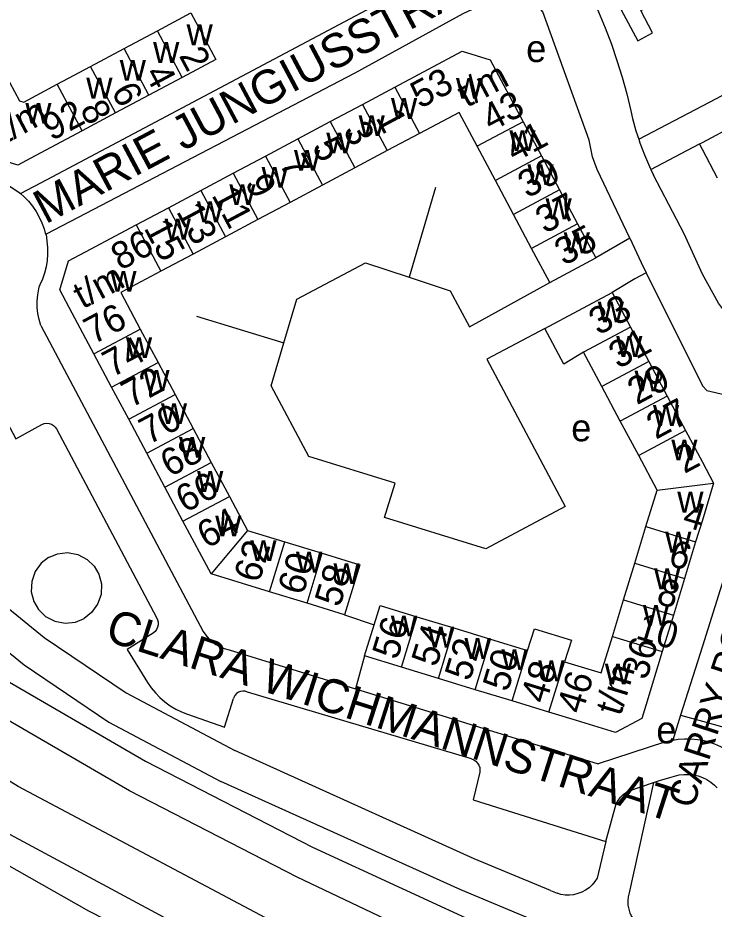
# Model space of a CAD drawing. Extents: x 159902 to 161769, y 383692 to 384875.
# Drawn here: x 160598.8 to 160701.7, y 383771.4 to 383903 of the extents above; entities that cross this region are included whole.
import ezdxf

# ---------------------------------------------------------------- set-up
doc = ezdxf.new("R2010")
doc.units = 0
for name, color, linetype in [('BLT_Basislijn', 7, 'Continuous'), ('BLT_Bebouwing', 7, 'Continuous'), ('BLT_Centroide', 7, 'Continuous'), ('BLT_Huisnummer', 7, 'Continuous'), ('BLT_Huisnummer_ tussenligend', 7, 'Continuous'), ('BLT_Huisnummer_reeks', 7, 'Continuous'), ('BLT_Onderverdeling_panden', 7, 'Continuous'), ('BLT_Spoorlijn', 7, 'Continuous'), ('BLT_Straatnaam', 7, 'Continuous'), ('BLT_Straatnaam_verkleind', 7, 'Continuous')]:
    doc.layers.add(name, color=color, linetype=linetype)

msp = doc.modelspace()

# ---------------------------------------------------------------- linework, layer by layer
at = {"layer": 'BLT_Basislijn'}
for p, q in [((160700, 383890.04), (160746.59, 383914.49)), ((160690.61, 383885.08), (160700, 383890.04)), ((160692.39, 383880.62), (160699.57, 383884.4)), ((160692.39, 383880.62), (160692.79, 383879.79)), ((160599.22, 383877.05), (160603.18, 383879.15)), ((160660.56, 383877.98), (160656.69, 383864.7)), ((160606.51, 383872.87), (160603.03, 383871.05)), ((160689.27, 383870.48), (160684.24, 383867.55)), ((160691.72, 383865.36), (160700, 383848.64)), ((160625.22, 383858.96), (160638.15, 383855)), ((160602.22, 383857.56), (160626.24, 383812.37)), ((160604.52, 383842.33), (160619.33, 383814.43)), ((160647.11, 383814.85), (160651.5, 383813.38)), ((160700, 383810.22), (160696.79, 383800)), ((160630.04, 383809.66), (160648.74, 383803.9)), ((160650.08, 383808.76), (160648.74, 383803.9)), ((160665.88, 383793.57), (160632.75, 383803.43)), ((160648.74, 383803.9), (160684.61, 383792.85)), ((160696.79, 383800), (160695.64, 383796.34)), ((160696.79, 383800), (160700, 383799.11)), ((160700, 383799.11), (160704.39, 383797.89)), ((160694.57, 383796.09), (160684.61, 383792.85)), ((160667.1, 383791.62), (160666.13, 383787.5)), ((160689.04, 383788.79), (160692.78, 383790.07)), ((160692.78, 383790.07), (160689.16, 383773.78)), ((160692.78, 383790.07), (160693.67, 383790.37)), ((160693.67, 383790.37), (160695.21, 383790.79)), ((160666.13, 383787.5), (160685.72, 383781.35)), ((160685.72, 383781.35), (160687.26, 383786.93)), ((160685.72, 383781.35), (160684.46, 383775.96)), ((160642.4, 383780.51), (160683.65, 383761.53)), ((160677.54, 383774.1), (160678.55, 383773.7))]:
    msp.add_line(p, q, dxfattribs=at)
for points in [[(160681.26, 383910.86), (160682.46, 383908.59), (160683.59, 383906.28), (160684.65, 383903.93), (160685.64, 383901.56), (160686.55, 383899.15), (160687.38, 383896.72), (160688.14, 383894.26), (160688.83, 383891.78), (160689.43, 383889.28), (160689.68, 383888.16)], [(160689.27, 383870.48), (160684.45, 383880.61), (160683.78, 383882.49), (160683.26, 383884.97), (160676.41, 383903.93), (160674.94, 383905.66), (160673.06, 383906.41), (160670.67, 383906.49), (160664.62, 383903.62), (160648.63, 383894.85), (160606.51, 383872.87)], [(160603.18, 383879.15), (160651.15, 383904.6), (160651.93, 383905.02)], [(160785.77, 383902.89), (160787.4, 383898.79), (160793.37, 383890.07), (160793.61, 383887.33), (160792.51, 383884.49), (160789.92, 383882.31), (160785.09, 383879.14), (160780.99, 383877.27), (160776.2, 383874.72), (160756.99, 383863.99), (160732.18, 383850.87), (160729.15, 383850.07), (160725.97, 383850.07), (160724.04, 383850.51), (160723.96, 383850.67), (160708.54, 383855.73), (160705.6, 383857.28), (160703.88, 383858.91), (160702.38, 383860.87), (160700, 383865.16)], [(160689.68, 383888.16), (160690.19, 383886.35), (160690.61, 383885.08)], [(160690.61, 383885.08), (160690.78, 383884.56), (160691.44, 383882.8), (160692.18, 383881.07), (160692.39, 383880.62)], [(160494.74, 383882.47), (160534.14, 383847.21), (160538.7, 383844.28), (160543.1, 383841.91), (160550.59, 383840.28), (160557.96, 383839.05), (160562.54, 383837.97), (160575.03, 383827.56), (160599.76, 383807.45), (160612.28, 383798.99), (160628.85, 383790.24)], [(160700, 383865.16), (160697.3, 383871.1), (160692.79, 383879.79)], [(160595.73, 383879.04), (160596.61, 383878.69), (160597.46, 383878.27), (160598.26, 383877.78), (160599.03, 383877.22), (160599.22, 383877.05)], [(160599.22, 383877.05), (160599.74, 383876.6), (160600.4, 383875.92), (160601, 383875.19), (160601.53, 383874.41), (160602, 383873.59), (160602.39, 383872.73), (160602.71, 383871.84), (160602.94, 383871.01)], [(160603.03, 383871.05), (160603.21, 383869.05), (160603.22, 383868.11), (160603.15, 383867.17), (160603, 383866.23), (160602.77, 383865.32), (160602.46, 383864.42), (160602.08, 383863.56), (160602.03, 383863.45)], [(160689.27, 383870.48), (160690.96, 383866.88), (160691.72, 383865.36)], [(160638.15, 383855), (160640.06, 383861.45), (160650.19, 383866.85), (160656.69, 383864.7)], [(160691.72, 383865.36), (160690, 383864.48), (160686.66, 383862.43)], [(160656.69, 383864.7), (160662.72, 383862.7), (160665.59, 383857.4), (160677.44, 383863.93)], [(160602.22, 383857.56), (160601.97, 383858.44), (160601.8, 383859.34), (160601.71, 383860.25), (160601.7, 383861.17), (160601.77, 383862.08), (160601.92, 383862.98), (160602.03, 383863.45)], [(160588.63, 383859.42), (160598.52, 383840.83), (160602.38, 383842.97)], [(160676.73, 383857.15), (160668.15, 383852.6), (160679.7, 383830.83), (160667.99, 383824.59), (160653.04, 383829.22), (160654.59, 383834.29), (160641.82, 383838.24), (160636.28, 383848.68), (160638.15, 383855)], [(160700, 383848.64), (160700.67, 383847.99), (160705.56, 383846.86), (160706.89, 383846.34), (160708.7, 383844.59), (160709.23, 383843.12), (160709.29, 383840.38), (160707.84, 383835.19), (160700, 383810.22)], [(160602.38, 383842.97), (160602.72, 383843.09), (160603.08, 383843.14), (160603.44, 383843.1), (160603.79, 383842.99), (160604.1, 383842.8), (160604.36, 383842.55), (160604.52, 383842.33)], [(160685.49, 383755.81), (160663.23, 383765.09), (160640.11, 383776.07), (160615.32, 383788.84), (160570.09, 383815.07), (160559.86, 383821.42), (160549.35, 383829.03)], [(160603.38, 383823.31), (160602.27, 383822.45), (160601.38, 383821.23), (160600.88, 383819.75), (160600.82, 383818.21), (160601.19, 383816.8), (160601.88, 383815.61), (160602.93, 383814.59), (160604.3, 383813.88), (160605.84, 383813.6), (160607.34, 383813.77), (160608.63, 383814.3)], [(160603.38, 383823.31), (160604.67, 383823.85), (160606.17, 383824.02), (160607.71, 383823.74), (160609.07, 383823.02), (160610.12, 383822.01), (160610.82, 383820.82), (160611.19, 383819.41), (160611.13, 383817.86), (160610.62, 383816.39), (160609.74, 383815.17), (160608.63, 383814.3)], [(160590.85, 383821.13), (160602.74, 383811.47), (160614.85, 383803.29), (160630.92, 383794.79)], [(160572.6, 383819.39), (160617.72, 383793.23), (160642.4, 383780.51)], [(160619.33, 383814.43), (160619.48, 383814.09), (160619.56, 383813.73), (160619.56, 383813.36), (160619.49, 383813), (160619.33, 383812.66), (160619.11, 383812.37), (160618.81, 383812.12)], [(160626.24, 383812.37), (160626.62, 383811.81), (160627.06, 383811.3), (160627.56, 383810.84), (160628.11, 383810.44), (160628.71, 383810.11), (160629.34, 383809.85), (160630.04, 383809.66)], [(160618.81, 383812.12), (160615.01, 383809.71), (160618, 383804.82)], [(160618, 383804.82), (160618.55, 383804.03), (160619.17, 383803.29), (160619.84, 383802.61), (160620.57, 383801.98), (160621.35, 383801.41), (160622.17, 383800.91), (160623.03, 383800.49), (160623.89, 383800.14)], [(160632.75, 383803.43), (160632.43, 383803.54), (160632.08, 383803.57), (160631.74, 383803.52), (160631.43, 383803.39), (160631.15, 383803.2), (160630.92, 383802.94), (160630.76, 383802.64), (160630.7, 383802.46)], [(160623.89, 383800.14), (160629.35, 383798.24), (160630.7, 383802.46)], [(160695.64, 383796.34), (160696.43, 383796.47), (160697.38, 383796.54), (160698.33, 383796.53), (160699.27, 383796.43), (160700, 383796.31)], [(160694.57, 383796.09), (160695.49, 383796.32), (160695.64, 383796.34)], [(160700, 383796.31), (160700.92, 383796.08), (160701.82, 383795.77), (160702.69, 383795.39), (160703.53, 383794.94)], [(160677.54, 383774.1), (160666.29, 383778.79), (160630.92, 383794.79)], [(160665.88, 383793.57), (160666.23, 383793.43), (160666.53, 383793.22), (160666.78, 383792.95), (160666.97, 383792.63), (160667.09, 383792.28), (160667.12, 383791.91), (160667.1, 383791.62)], [(160695.21, 383790.79), (160695.87, 383791.02), (160696.56, 383791.18), (160697.26, 383791.27), (160697.97, 383791.27), (160698.67, 383791.19), (160699.36, 383791.03), (160700, 383790.81)], [(160686.08, 383765.12), (160664.3, 383774.2), (160628.85, 383790.24)], [(160700, 383790.81), (160700.64, 383790.5), (160701.23, 383790.13), (160701.79, 383789.69), (160702.21, 383789.27)], [(160687.26, 383786.93), (160687.54, 383787.43), (160687.9, 383787.89), (160688.32, 383788.3), (160688.78, 383788.64), (160689.04, 383788.79)], [(160684.46, 383775.96), (160684.12, 383775.43), (160683.71, 383774.95), (160683.25, 383774.53), (160682.74, 383774.17), (160682.18, 383773.87), (160681.59, 383773.65), (160680.98, 383773.5), (160680.35, 383773.44), (160679.73, 383773.45), (160679.1, 383773.54), (160678.55, 383773.7)], [(160689.16, 383773.78), (160689.03, 383773.18), (160688.98, 383772.57), (160689.01, 383771.95), (160689.12, 383771.35), (160689.3, 383770.76), (160689.57, 383770.21), (160689.9, 383769.69), (160690.29, 383769.22), (160690.74, 383768.8), (160691.25, 383768.45), (160691.75, 383768.19)]]:
    msp.add_lwpolyline(points, dxfattribs=at)
at = {"layer": 'BLT_Bebouwing'}
for p, q in [((160614.53, 383898.48), (160619.47, 383901.11)), ((160609.59, 383895.84), (160614.53, 383898.48)), ((160604.65, 383893.21), (160609.59, 383895.84)), ((160623.14, 383894.23), (160618.2, 383891.6)), ((160649.77, 383890.24), (160654.55, 383892.79)), ((160618.2, 383891.6), (160613.26, 383888.97)), ((160644.99, 383887.7), (160649.77, 383890.24)), ((160613.26, 383888.97), (160608.32, 383886.34)), ((160640.21, 383885.15), (160644.99, 383887.7)), ((160673.54, 383887.66), (160676.21, 383882.63)), ((160700, 383884.62), (160706.39, 383888.02)), ((160608.32, 383886.34), (160601.39, 383882.65)), ((160635.43, 383882.61), (160640.21, 383885.15)), ((160658.19, 383885.94), (160653.42, 383883.4)), ((160669.41, 383879.01), (160666.73, 383884.04)), ((160699.57, 383884.4), (160700, 383884.62)), ((160700, 383883.59), (160699.57, 383884.4)), ((160702.26, 383879.33), (160700, 383883.59)), ((160630.65, 383880.06), (160635.43, 383882.61)), ((160653.42, 383883.4), (160648.64, 383880.85)), ((160676.21, 383882.63), (160678.89, 383877.61)), ((160648.64, 383880.85), (160643.86, 383878.3)), ((160625.87, 383877.52), (160630.65, 383880.06)), ((160643.86, 383878.3), (160639.08, 383875.76)), ((160672.09, 383873.98), (160669.41, 383879.01)), ((160621.09, 383874.97), (160625.87, 383877.52)), ((160678.89, 383877.61), (160681.57, 383872.58)), ((160639.08, 383875.76), (160634.3, 383873.22)), ((160616.31, 383872.43), (160621.09, 383874.97)), ((160634.3, 383873.22), (160629.52, 383870.67)), ((160674.77, 383868.96), (160672.09, 383873.98)), ((160608.85, 383868.45), (160616.31, 383872.43)), ((160681.57, 383872.58), (160684.24, 383867.55)), ((160629.52, 383870.67), (160624.74, 383868.12)), ((160677.44, 383863.93), (160674.77, 383868.96)), ((160624.74, 383868.12), (160619.96, 383865.58)), ((160677.44, 383863.93), (160684.24, 383867.55)), ((160676.73, 383857.15), (160686.66, 383862.43)), ((160686.66, 383862.43), (160689.38, 383857.33)), ((160610.06, 383853.38), (160606.85, 383859.41)), ((160689.38, 383857.33), (160692.09, 383852.24)), ((160616.93, 383857.03), (160619.56, 383852.1)), ((160612.69, 383848.45), (160610.06, 383853.38)), ((160685.16, 383848.54), (160682.44, 383853.64)), ((160619.56, 383852.1), (160622.07, 383847.38)), ((160692.09, 383852.24), (160694.81, 383847.14)), ((160615.21, 383843.72), (160612.69, 383848.45)), ((160687.87, 383843.45), (160685.16, 383848.54)), ((160622.07, 383847.38), (160624.75, 383842.36)), ((160694.81, 383847.14), (160697.52, 383842.05)), ((160617.88, 383838.7), (160615.21, 383843.72)), ((160690.59, 383838.35), (160687.87, 383843.45)), ((160624.75, 383842.36), (160627.42, 383837.34)), ((160697.52, 383842.05), (160700, 383837.39)), ((160620.55, 383833.69), (160617.88, 383838.7)), ((160627.42, 383837.34), (160630.09, 383832.33)), ((160693.3, 383833.26), (160690.59, 383838.35)), ((160700, 383837.39), (160701.66, 383834.28)), ((160623.23, 383828.67), (160620.55, 383833.69)), ((160701.66, 383834.28), (160700, 383828.84)), ((160630.09, 383832.33), (160632.76, 383827.31)), ((160691.65, 383827.86), (160693.3, 383833.26)), ((160627.38, 383820.88), (160623.23, 383828.67)), ((160700, 383828.84), (160699.01, 383825.61)), ((160632.76, 383827.31), (160638.3, 383825.62)), ((160690, 383822.46), (160691.65, 383827.86)), ((160638.3, 383825.62), (160643.83, 383823.93)), ((160699.01, 383825.61), (160697.37, 383820.21)), ((160688.36, 383817.05), (160690, 383822.46)), ((160636.04, 383818.23), (160627.38, 383820.88)), ((160697.37, 383820.21), (160695.72, 383814.81)), ((160641.58, 383816.54), (160636.04, 383818.23)), ((160686.71, 383811.65), (160688.36, 383817.05)), ((160657.81, 383814.56), (160663.26, 383812.9)), ((160695.72, 383814.81), (160694.07, 383809.41)), ((160663.26, 383812.9), (160668.71, 383811.24)), ((160668.71, 383811.24), (160674.16, 383809.58)), ((160694.07, 383809.41), (160691.64, 383801.43)), ((160660.99, 383805.43), (160655.54, 383807.09)), ((160666.43, 383803.77), (160660.99, 383805.43)), ((160671.88, 383802.11), (160666.43, 383803.77)), ((160677.33, 383800.44), (160671.88, 383802.11)), ((160681.39, 383799.21), (160677.33, 383800.44))]:
    msp.add_line(p, q, dxfattribs=at)
for points in [[(160686.52, 383911.13), (160684.82, 383910.21), (160690.46, 383899.61), (160692.65, 383900.78), (160690.89, 383904.09), (160693.18, 383905.31)], [(160619.47, 383901.11), (160624.41, 383903.74), (160628.07, 383896.86), (160623.14, 383894.23)], [(160654.55, 383892.79), (160664.48, 383898.08), (160668.66, 383896.81), (160673.54, 383887.66)], [(160597.6, 383893.5), (160599.05, 383890.78), (160599.71, 383890.58), (160604.65, 383893.21)], [(160666.73, 383884.04), (160664.06, 383889.06), (160658.19, 383885.94)], [(160601.39, 383882.65), (160598.81, 383881.27), (160594.71, 383882.52), (160592.95, 383885.83)], [(160606.85, 383859.41), (160605.02, 383862.85), (160606.32, 383867.11), (160608.85, 383868.45)], [(160619.96, 383865.58), (160614.06, 383862.43), (160616.93, 383857.03)], [(160682.44, 383853.64), (160679.55, 383851.87), (160676.73, 383857.15)], [(160643.83, 383823.93), (160649.37, 383822.24), (160647.11, 383814.85)], [(160647.11, 383814.85), (160641.58, 383816.54)], [(160651.5, 383813.38), (160652.36, 383816.23), (160657.81, 383814.56)], [(160650.08, 383808.76), (160651.5, 383813.38)], [(160674.16, 383809.58), (160675.18, 383812.78), (160680.64, 383811.1), (160679.61, 383807.91)], [(160679.61, 383807.91), (160685.06, 383806.25), (160686.71, 383811.65)], [(160655.54, 383807.09), (160650.08, 383808.76)], [(160691.64, 383801.43), (160691.05, 383799.5), (160687.18, 383797.44), (160681.39, 383799.21)]]:
    msp.add_lwpolyline(points, dxfattribs=at)
at = {"layer": 'BLT_Onderverdeling_panden'}
for p, q in [((160623.14, 383894.23), (160619.47, 383901.11)), ((160618.2, 383891.6), (160614.53, 383898.48)), ((160613.26, 383888.97), (160609.59, 383895.84)), ((160608.32, 383886.34), (160604.65, 383893.21)), ((160654.55, 383892.79), (160658.19, 383885.94)), ((160649.77, 383890.24), (160653.41, 383883.4)), ((160673.54, 383887.66), (160666.73, 383884.04)), ((160676.21, 383882.63), (160669.41, 383879.01)), ((160630.65, 383880.06), (160634.3, 383873.22)), ((160625.87, 383877.52), (160629.52, 383870.67)), ((160678.89, 383877.61), (160672.09, 383873.98)), ((160621.09, 383874.97), (160624.74, 383868.12)), ((160616.31, 383872.43), (160619.96, 383865.58)), ((160681.57, 383872.58), (160674.77, 383868.96)), ((160689.38, 383857.33), (160682.44, 383853.64)), ((160610.06, 383853.38), (160616.93, 383857.03)), ((160612.69, 383848.45), (160619.56, 383852.1)), ((160692.09, 383852.24), (160685.16, 383848.54)), ((160615.21, 383843.72), (160622.07, 383847.38)), ((160694.81, 383847.14), (160687.87, 383843.45)), ((160617.88, 383838.7), (160624.75, 383842.36)), ((160697.52, 383842.05), (160690.59, 383838.35)), ((160620.55, 383833.69), (160627.42, 383837.34)), ((160693.3, 383833.26), (160700, 383834.07)), ((160700, 383834.07), (160701.66, 383834.28)), ((160623.23, 383828.67), (160630.09, 383832.33)), ((160632.76, 383827.31), (160627.38, 383820.88)), ((160691.65, 383827.86), (160699.01, 383825.61)), ((160636.04, 383818.23), (160638.3, 383825.62)), ((160641.58, 383816.54), (160643.83, 383823.93)), ((160690, 383822.46), (160697.37, 383820.21)), ((160688.36, 383817.05), (160695.72, 383814.81)), ((160655.54, 383807.09), (160657.81, 383814.56)), ((160660.99, 383805.43), (160663.26, 383812.9)), ((160666.43, 383803.77), (160668.71, 383811.24)), ((160686.71, 383811.65), (160694.07, 383809.41)), ((160671.88, 383802.11), (160674.16, 383809.58)), ((160677.33, 383800.44), (160679.61, 383807.91))]:
    msp.add_line(p, q, dxfattribs=at)
for points in [[(160644.99, 383887.7), (160648.64, 383880.85)], [(160640.21, 383885.15), (160643.86, 383878.3)], [(160635.43, 383882.61), (160639.08, 383875.76)]]:
    msp.add_lwpolyline(points, dxfattribs=at)
at = {"layer": 'BLT_Spoorlijn'}
for points in [[(160793.13, 383713.32), (160766.04, 383720.12), (160726.94, 383731.96), (160686.31, 383747.06), (160640.98, 383767.11), (160598.87, 383789.48), (160558.68, 383814.33), (160516.13, 383845.06)], [(160566.71, 383800.78), (160595.62, 383783.46), (160626.93, 383766.69), (160664.31, 383749), (160682.91, 383741.08)], [(160559.53, 383800.41), (160582.92, 383786.04), (160609.25, 383771.11), (160628.77, 383761.16), (160650.68, 383750.29), (160671.86, 383741.08), (160684.94, 383735.73)]]:
    msp.add_lwpolyline(points, dxfattribs=at)

# ---------------------------------------------------------------- texts
at = {"layer": 'BLT_Centroide'}
for s, p in [('w', (160623.77, 383898.98)), ('w', (160618.83, 383896.36)), ('e', (160673.96, 383896.49)), ('w', (160613.89, 383893.72)), ('w', (160608.95, 383891.09)), ('w', (160663.59, 383891.06)), ('w', (160599.94, 383887.38)), ('w', (160653.98, 383888.09)), ('w', (160649.2, 383885.55)), ('w', (160644.42, 383883)), ('w', (160671.48, 383883.34)), ('w', (160639.64, 383880.45)), ('w', (160634.86, 383877.92)), ('w', (160674.15, 383878.31)), ('w', (160630.09, 383875.36)), ('w', (160625.31, 383872.83)), ('w', (160676.83, 383873.28)), ('w', (160620.53, 383870.27)), ('w', (160679.51, 383868.25)), ('w', (160612.5, 383862.55)), ('w', (160684.55, 383858.03)), ('w', (160614.81, 383852.75)), ('w', (160687.27, 383852.94)), ('w', (160617.38, 383847.91)), ('w', (160689.98, 383847.84)), ('w', (160619.98, 383843.03)), ('w', (160692.7, 383842.75)), ('e', (160680.62, 383840.47)), ('w', (160622.66, 383838.03)), ('w', (160695.41, 383837.66)), ('w', (160625.33, 383833)), ('w', (160696.3, 383829.94)), ('w', (160628, 383826.42)), ('w', (160694.51, 383824.03)), ('w', (160633.2, 383822.78)), ('w', (160639.94, 383821.08)), ('w', (160645.47, 383819.39)), ('w', (160692.87, 383818.62)), ('w', (160691.21, 383813.22)), ('w', (160653.95, 383811.66)), ('w', (160659.41, 383810)), ('w', (160664.84, 383808.33)), ('w', (160670.3, 383806.67)), ('w', (160675.75, 383805.02)), ('w', (160685.59, 383804.56)), ('e', (160693.2, 383795.85))]:
    msp.add_text(s, height=4, dxfattribs=at).set_placement(p)
at = {"layer": 'BLT_Huisnummer'}
for s, rotation, p in [('2', 298.0422, (160622.58, 383897.44)), ('8', 298.0457, (160607.93, 383889.54)), ('1', 298.0416, (160651.65, 383888.29)), ('41', 28.0384, (160672.24, 383881.6)), ('5', 298.0382, (160642.23, 383884.02)), ('39', 28.0384, (160674.12, 383876.3)), ('9', 298.0416, (160632.32, 383878.66)), ('15', 298.0416, (160617.39, 383871.98)), ('35', 28.0395, (160679.54, 383866.33)), ('33', 28.0395, (160684.61, 383856.06)), ('74', 28.0409, (160612.74, 383849.83)), ('27', 28.0395, (160693.12, 383840.68)), ('70', 28.0409, (160618.15, 383839.9)), ('2', 28.0395, (160697.34, 383835.63)), ('66', 28.0409, (160623.55, 383829.83)), ('62', 73.0287, (160634.49, 383819.41)), ('6', 343.0319, (160694.77, 383822.21)), ('58', 73.0337, (160646.42, 383815.83)), ('56', 73.0337, (160654.92, 383808.06)), ('10', 343.0347, (160689.99, 383811.4)), ('52', 73.0337, (160665.64, 383804.9)), ('48', 73.0359, (160676.87, 383801.57))]:
    msp.add_text(s, height=4, rotation=rotation, dxfattribs=at).set_placement(p)
at = {"layer": 'BLT_Huisnummer_ tussenligend'}
for s, rotation, p in [('4', 298.0422, (160617.48, 383894.81)), ('6', 298.0422, (160612.56, 383892.17)), ('3', 298.0416, (160646.83, 383886.4)), ('7', 298.0382, (160637.39, 383881.53)), ('11', 298.0416, (160627.4, 383876.85)), ('37', 28.0395, (160676.72, 383871.07)), ('13', 298.0416, (160622.18, 383874.43)), ('31', 28.0395, (160687.55, 383851.1)), ('72', 28.0409, (160615.53, 383845.35)), ('29', 28.0395, (160690.31, 383845.78)), ('68', 28.0409, (160621.28, 383835.11)), ('4', 343.0319, (160696.87, 383828.01)), ('64', 28.0409, (160626.71, 383824.55)), ('60', 73.0337, (160640.97, 383817.58)), ('8', 343.0319, (160693.02, 383816.58)), ('54', 73.0337, (160660.72, 383806.99)), ('50', 73.0359, (160671.25, 383803.32))]:
    msp.add_text(s, height=4, rotation=rotation, dxfattribs=at).set_placement(p)
at = {"layer": 'BLT_Huisnummer_reeks'}
for s, rotation, p in [('53', 28.0378, (160658.26, 383889.53)), ('t/m', 28.0393, (160665.16, 383889.69)), ('43', 28.0384, (160668.77, 383886.14)), ('t/m', 28.0427, (160596.96, 383884.38)), ('92', 28.0427, (160603.8, 383884.77)), ('86', 28.0378, (160613.98, 383865.63)), ('t/m', 28.0393, (160608.4, 383859.94)), ('76', 28.0409, (160609.99, 383854.71)), ('36', 73.0335, (160691.76, 383805.06)), ('t/m', 73.0335, (160687.92, 383799.77)), ('46', 73.0359, (160682.23, 383800.05))]:
    msp.add_text(s, height=4, rotation=rotation, dxfattribs=at).set_placement(p)
at = {"layer": 'BLT_Straatnaam'}
for s, height, rotation, p in [('MARIE JUNGIUSSTRAAT', 5, 28.0378, (160602.91, 383872.48)), ('CLARA WICHMANNSTRAAT', 4.9999, 342.2058, (160611.54, 383811.09))]:
    msp.add_text(s, height=height, rotation=rotation, dxfattribs=at).set_placement(p)
at = {"layer": 'BLT_Straatnaam_verkleind'}
msp.add_text('CARRY POTHUIS-SMITSTRAAT', height=3.9999, rotation=71.8854, dxfattribs=at).set_placement((160698.62, 383786.06))

doc.saveas('drawing.dxf')
